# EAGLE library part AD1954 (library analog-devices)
SigmaDSP? 3-Channel, 26-Bit Signal Processing DAC Auto generated by make-symbol-device-package-bsdl.ulp Rev. 33 Source: http://www.analog.com/static/imported-files/data_sheets/AD1954.pdf
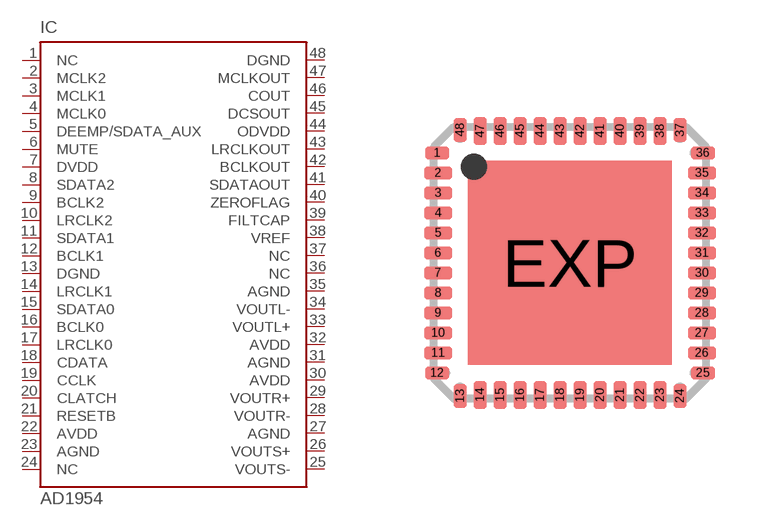
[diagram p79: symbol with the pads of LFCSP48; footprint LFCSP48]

Designator prefix IC

## AD1954 (MPN: AD1954YSTZ; OC_FARNELL: unknown; OC_NEWARK: 12M8458)  [LFCSP48]
1  NC  nc
2  MCLK2  in
3  MCLK1  in
4  MCLK0  in
5  DEEMP/SDATA_AUX  in
6  MUTE  in
7  DVDD  pwr
8  SDATA2  in
9  BCLK2  in
10  LRCLK2  in
11  SDATA1  in
12  BCLK1  in
13  DGND  pwr
14  LRCLK1  in
15  SDATA0  in
16  BCLK0  in
17  LRCLK0  in
18  CDATA  in
19  CCLK  in
20  CLATCH  in
21  RESETB  in
22  AVDD  pwr
23  AGND  pwr
24  NC  nc
25  VOUTS-  out
26  VOUTS+  out
27  AGND  pwr
28  VOUTR-  out
29  VOUTR+  out
30  AVDD  pwr
31  AGND  pwr
32  AVDD  pwr
33  VOUTL+  out
34  VOUTL-  out
35  AGND  pwr
36  NC  nc
37  NC  nc
38  VREF  in
39  FILTCAP  in
40  ZEROFLAG  out
41  SDATAOUT  out
42  BCLKOUT  out
43  LRCLKOUT  out
44  ODVDD  pwr
45  DCSOUT  out
46  COUT  out
47  MCLKOUT  out
48  DGND  pwr

## Footprint LFCSP48 (pad centres in mm)
Lead Frame Chip Scale Package LFCSP CP-48 COMPLIANT TO JEDEC STANDARDS MO-220-VKKD-2 Source: http://www.analog.com/UploadedFiles/Data_Sheets/39780344872292AD7651_0.pdf
smd 0.6 x 0.32: 1 -3.325,2.75; 12 -3.325,-2.75; 25 3.325,-2.75; 36 3.325,2.75
smd 0.7 x 0.32: 2 -3.3,2.25; 3 -3.3,1.75; 4 -3.3,1.25; 5 -3.3,0.75; 6 -3.3,0.25; 7 -3.3,-0.25; 8 -3.3,-0.75; 9 -3.3,-1.25; 10 -3.3,-1.75; 11 -3.3,-2.25; 26 3.3,-2.25; 27 3.3,-1.75; 28 3.3,-1.25; 29 3.3,-0.75; 30 3.3,-0.25; 31 3.3,0.25; 32 3.3,0.75; 33 3.3,1.25; 34 3.3,1.75; 35 3.3,2.25
smd 0.32 x 0.6: 13 -2.75,-3.325; 24 2.75,-3.325; 37 2.75,3.325; 48 -2.75,3.325
smd 0.32 x 0.7: 14 -2.25,-3.3; 15 -1.75,-3.3; 16 -1.25,-3.3; 17 -0.75,-3.3; 18 -0.25,-3.3; 19 0.25,-3.3; 20 0.75,-3.3; 21 1.25,-3.3; 22 1.75,-3.3; 23 2.25,-3.3; 38 2.25,3.3; 39 1.75,3.3; 40 1.25,3.3; 41 0.75,3.3; 42 0.25,3.3; 43 -0.25,3.3; 44 -0.75,3.3; 45 -1.25,3.3; 46 -1.75,3.3; 47 -2.25,3.3
smd 5.1 x 5.1: EXP 0,0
